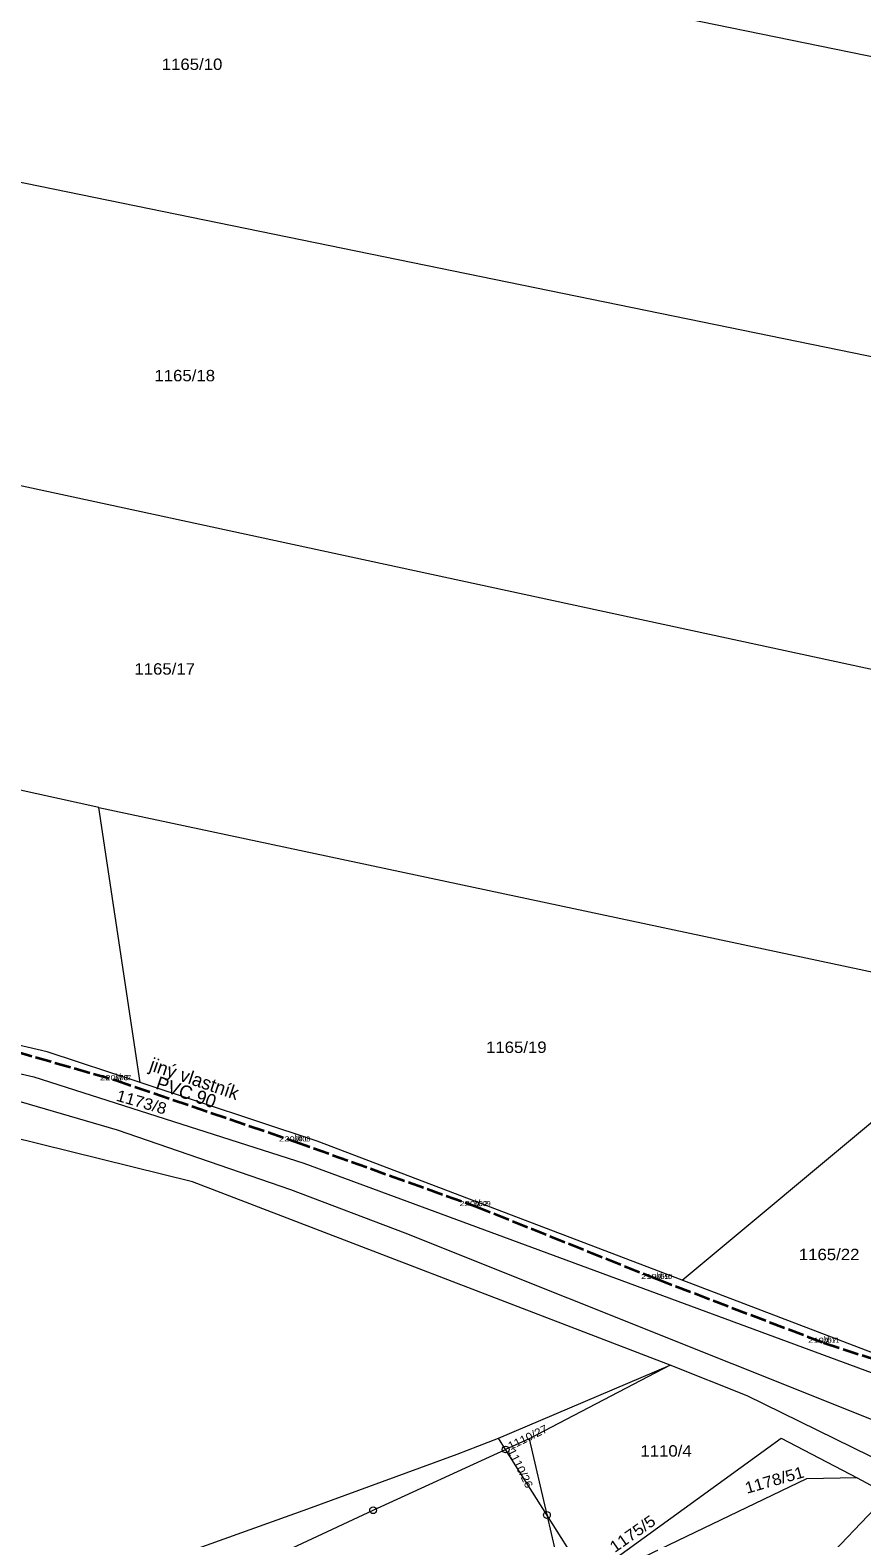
# Model space of a CAD drawing. Extents: x -686207 to -681951, y -1020493 to -1017811.
# Drawn here: x -684095.1 to -683971.1, y -1019290.6 to -1019065.6 of the extents above; entities that cross this region are included whole.
import ezdxf
from ezdxf.enums import TextEntityAlignment as Align

# ---------------------------------------------------------------- set-up
doc = ezdxf.new("R2010")
doc.units = 0
doc.header["$LTSCALE"] = 0.4
doc.header["$PDMODE"] = 32
doc.header["$PDSIZE"] = 0.2
doc.linetypes.add('LONG_DASHED', pattern=[7.5, 6, -1.5])
for name, color, linetype, lineweight in [('1', 7, 'Continuous', 13), ('3', 7, 'Continuous', 13), ('35', 7, 'LONG_DASHED', 35), ('4', 7, 'Continuous', 13), ('6', 7, 'Continuous', 13), ('8', 7, 'Continuous', 13)]:
    doc.layers.add(name, color=color, linetype=linetype, lineweight=lineweight)
doc.layers.add('17', color=7, linetype='Continuous')
doc.layers.add('2', color=7, linetype='Continuous')

msp = doc.modelspace()

# ---------------------------------------------------------------- linework, layer by layer
at = {"layer": '1'}
for p, q in [((-683965.63, -1019070.44), (-684160.81, -1019030.34)), ((-684197.85, -1019067.57), (-683965.52, -1019115.17)), ((-683966.09, -1019161.81), (-684198.29, -1019111.69)), ((-684084.87, -1019181.63), (-684199.82, -1019156.49)), ((-684084.87, -1019181.63), (-683966.85, -1019206.74)), ((-684078.71, -1019222.69), (-684084.87, -1019181.63)), ((-683997.92, -1019252.17), (-683967.44, -1019226.77)), ((-683968.49, -1019263.4), (-683997.92, -1019252.17)), ((-684025.29, -1019275.77), (-683999.7, -1019264.85)), ((-683999.7, -1019264.85), (-684020.72, -1019275.84)), ((-684024.23, -1019277.45), (-684025.29, -1019275.77)), ((-684020.72, -1019275.84), (-684024.23, -1019277.45)), ((-683971.83, -1019281.7), (-683967.18, -1019284.14)), ((-684012.88, -1019295.44), (-684018.07, -1019287.22)), ((-684018.07, -1019287.22), (-684015.7, -1019297.38))]:
    msp.add_line(p, q, dxfattribs=at)
for points in [[(-684078.71, -1019222.69), (-684092.58, -1019218.1), (-684205.44, -1019191.78)], [(-684203.15, -1019196.83), (-684094.57, -1019221.82), (-684054.3, -1019234.73), (-683955.31, -1019271.3)], [(-683999.7, -1019264.85), (-684070.91, -1019237.48), (-684193.78, -1019207.13)], [(-683997.92, -1019252.17), (-684052.31, -1019231.43), (-684078.71, -1019222.69)], [(-684186.57, -1019227.46), (-684168.7, -1019292.93), (-684162.9, -1019304.17), (-684155.58, -1019310.4), (-684144.67, -1019314.55), (-684130.54, -1019316.11), (-684119.38, -1019315.7), (-684115.21, -1019314.39), (-684083.87, -1019305.16), (-684044, -1019286.52), (-684024.23, -1019277.45)], [(-684186.57, -1019227.46), (-684162.32, -1019295.76), (-684152.44, -1019306.86), (-684142.29, -1019309.68), (-684120.17, -1019310.13), (-684053.74, -1019286.29), (-684031.45, -1019278.13), (-684025.29, -1019275.77)], [(-683964.59, -1019281.04), (-683988.22, -1019269.44), (-683999.7, -1019264.85)], [(-684020.72, -1019275.84), (-684018.07, -1019287.22), (-684024.23, -1019277.45)], [(-684012.06, -1019296.74), (-683983.16, -1019275.76), (-683971.83, -1019281.7)], [(-683971.83, -1019281.7), (-683979.37, -1019281.84), (-684015.28, -1019299.07)], [(-684071.5, -1019361.03), (-684026.9, -1019333.56), (-684000.31, -1019315.71), (-683986.41, -1019304.35), (-683967.18, -1019284.14)]]:
    msp.add_lwpolyline(points, dxfattribs=at)
for p in [(-684082.37, -1019222.33), (-684055.68, -1019231.47), (-684028.78, -1019241.13), (-684001.7, -1019252), (-683976.78, -1019261.52)]:
    msp.add_point(p, dxfattribs=at)
at = {"layer": '35'}
msp.add_lwpolyline([(-684253.32, -1019181.51), (-684218.74, -1019189.57), (-684187.75, -1019196.6), (-684161.31, -1019202.33), (-684135.19, -1019208.18), (-684108.74, -1019214.75), (-684082.37, -1019222.33), (-684055.68, -1019231.47), (-684028.78, -1019241.13), (-684001.7, -1019252), (-683976.78, -1019261.52), (-683963.28, -1019265.94), (-683954.22, -1019264.32), (-683949.59, -1019261.5)], dxfattribs=at)
at = {"layer": '6'}
for p, q in [((-684082.1, -1019229.81), (-684107.44, -1019222.4)), ((-683605.51, -1019418.83), (-684039.2, -1019245.15))]:
    msp.add_line(p, q, dxfattribs=at)
msp.add_lwpolyline([(-684039.2, -1019245.15), (-684056.24, -1019238.7), (-684082.1, -1019229.81)], dxfattribs=at)
at = {"layer": '8'}
for centre, radius in [((-684024.23, -1019277.4499), 0.5), ((-684024.23, -1019277.4499), 0.0303), ((-684044, -1019286.5199), 0.5), ((-684044, -1019286.5199), 0.0303), ((-684018.07, -1019287.2199), 0.5), ((-684018.07, -1019287.2199), 0.0303)]:
    msp.add_circle(centre, radius, dxfattribs=at)

# ---------------------------------------------------------------- texts
at = {"layer": '17'}
for s, p in [('jiný vlastník', (-684070.959, -1019223.0668)), ('PVC 90', (-684072.179, -1019225.0738))]:
    msp.add_text(s, height=2, rotation=341.096, dxfattribs=at).set_placement(p, align=Align.CENTER)
at = {"layer": '2', "width": 1.1}
for s, p in [('1165/10', (-684075.51, -1019071.57)), ('1165/18', (-684076.6, -1019118.03)), ('1165/17', (-684079.59, -1019161.809)), ('1165/19', (-684027.16, -1019218.27)), ('1165/22', (-683980.52, -1019249.19)), ('1110/4', (-684004.14, -1019278.51))]:
    msp.add_text(s, height=1.7, dxfattribs=at).set_placement(p)
at = {"layer": '2'}
for s, p in [('0007', (-684082.37, -1019222.33)), ('0008', (-684055.68, -1019231.47)), ('0009', (-684028.78, -1019241.13)), ('0010', (-684001.7, -1019252)), ('0011', (-683976.78, -1019261.52))]:
    msp.add_text(s, height=0.75, dxfattribs=at).set_placement(p)
at = {"layer": '2', "width": 1.1}
for s, height, rotation, p in [('1173/8', 1.7, 344, (-684082.424, -1019225.367)), ('1110/27', 1.19, 26, (-684023.519, -1019277.554)), ('1110/26', 1.19, 296, (-684023.944, -1019277.65)), ('1178/51', 1.7, 16, (-683988.265, -1019284.057)), ('1175/5', 1.7, 35, (-684007.962, -1019292.906))]:
    msp.add_text(s, height=height, rotation=rotation, dxfattribs=at).set_placement(p)
at = {"layer": '3', "width": 1.4}
for s, p in [('220 78 ', (-684082.37, -1019222.33)), ('220 41 ', (-684055.68, -1019231.47)), ('220 02 ', (-684028.78, -1019241.13)), ('219 69 ', (-684001.7, -1019252)), ('219 67 ', (-683976.78, -1019261.52))]:
    msp.add_text(s, height=0.75, dxfattribs=at).set_placement(p, align=Align.CENTER)
at = {"layer": '4', "width": 0.85}
for p in [(-684082.37, -1019222.33), (-684055.68, -1019231.47), (-684028.78, -1019241.13), (-684001.7, -1019252), (-683976.78, -1019261.52)]:
    msp.add_text('V', height=1, dxfattribs=at).set_placement(p)

doc.saveas('drawing.dxf')
